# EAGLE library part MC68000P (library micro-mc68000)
68xxx PROCESSOR
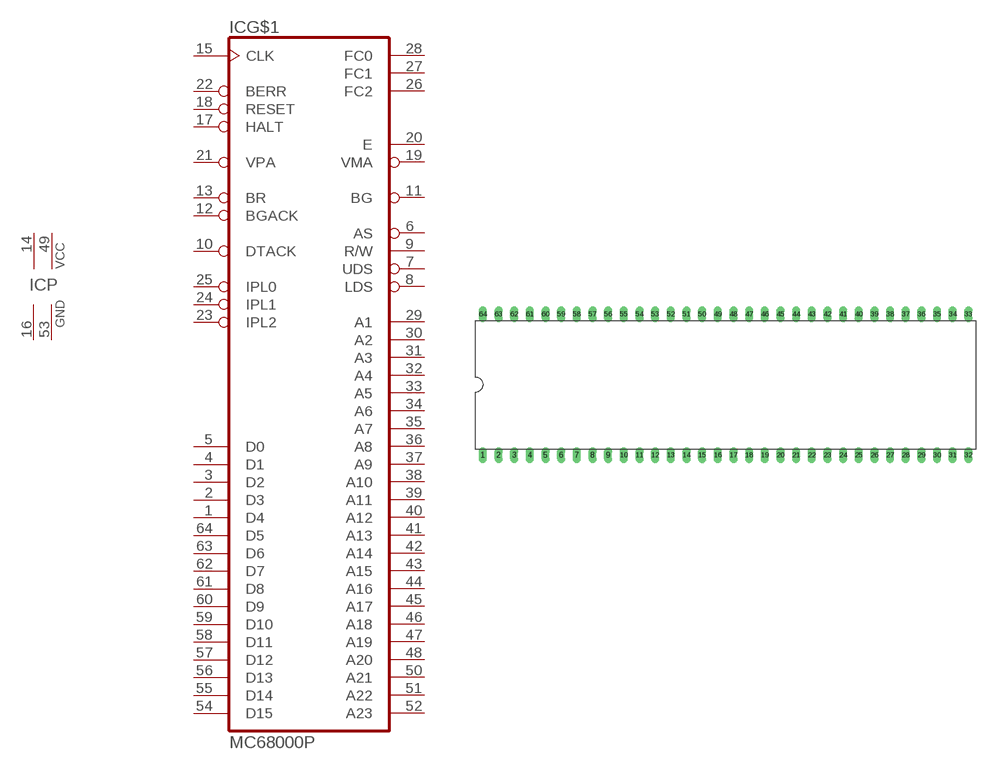
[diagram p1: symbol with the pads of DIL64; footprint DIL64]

Designator prefix IC; gates G$1=68000 P=2PWR2GND

## MC68000P (OC_FARNELL: unknown; OC_NEWARK: unknown)  [DIL64]
1  G$1:D4
2  G$1:D3
3  G$1:D2
4  G$1:D1
5  G$1:D0
6  G$1:AS  out
7  G$1:UDS  out
8  G$1:LDS  out
9  G$1:R/W  out
10  G$1:DTACK  in
11  G$1:BG  out
12  G$1:BGACK  in
13  G$1:BR  in
14  P:VCC  pwr
15  G$1:CLK  in
16  P:GND  pwr
17  G$1:HALT
18  G$1:RESET
19  G$1:VMA  out
20  G$1:E  out
21  G$1:VPA  in
22  G$1:BERR  in
23  G$1:IPL2  in
24  G$1:IPL1  in
25  G$1:IPL0  in
26  G$1:FC2  out
27  G$1:FC1  out
28  G$1:FC0  out
29  G$1:A1  out
30  G$1:A2  out
31  G$1:A3  out
32  G$1:A4  out
33  G$1:A5  out
34  G$1:A6  out
35  G$1:A7  out
36  G$1:A8  out
37  G$1:A9  out
38  G$1:A10  out
39  G$1:A11  out
40  G$1:A12  out
41  G$1:A13  out
42  G$1:A14  out
43  G$1:A15  out
44  G$1:A16  out
45  G$1:A17  out
46  G$1:A18  out
47  G$1:A19  out
48  G$1:A20  out
49  P:VCC  pwr
50  G$1:A21  out
51  G$1:A22  out
52  G$1:A23  out
53  P:GND  pwr
54  G$1:D15
55  G$1:D14
56  G$1:D13
57  G$1:D12
58  G$1:D11
59  G$1:D10
60  G$1:D9
61  G$1:D8
62  G$1:D7
63  G$1:D6
64  G$1:D5

## Footprint DIL64 (pad centres in mm)
Dual In Line
drill 0.813 long: 1 -39.37,-11.43; 2 -36.83,-11.43; 3 -34.29,-11.43; 4 -31.75,-11.43; 5 -29.21,-11.43; 6 -26.67,-11.43; 7 -24.13,-11.43; 8 -21.59,-11.43; 9 -19.05,-11.43; 10 -16.51,-11.43; 11 -13.97,-11.43; 12 -11.43,-11.43; 13 -8.89,-11.43; 14 -6.35,-11.43; 15 -3.81,-11.43; 16 -1.27,-11.43; 17 1.27,-11.43; 18 3.81,-11.43; 19 6.35,-11.43; 20 8.89,-11.43; 21 11.43,-11.43; 22 13.97,-11.43; 23 16.51,-11.43; 24 19.05,-11.43; 25 21.59,-11.43; 26 24.13,-11.43; 27 26.67,-11.43; 28 29.21,-11.43; 29 31.75,-11.43; 30 34.29,-11.43; 31 36.83,-11.43; 32 39.37,-11.43; 33 39.37,11.43; 34 36.83,11.43; 35 34.29,11.43; 36 31.75,11.43; 37 29.21,11.43; 38 26.67,11.43; 39 24.13,11.43; 40 21.59,11.43; 41 19.05,11.43; 42 16.51,11.43; 43 13.97,11.43; 44 11.43,11.43; 45 8.89,11.43; 46 6.35,11.43; 47 3.81,11.43; 48 1.27,11.43; 49 -1.27,11.43; 50 -3.81,11.43; 51 -6.35,11.43; 52 -8.89,11.43; 53 -11.43,11.43; 54 -13.97,11.43; 55 -16.51,11.43; 56 -19.05,11.43; 57 -21.59,11.43; 58 -24.13,11.43; 59 -26.67,11.43; 60 -29.21,11.43; 61 -31.75,11.43; 62 -34.29,11.43; 63 -36.83,11.43; 64 -39.37,11.43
